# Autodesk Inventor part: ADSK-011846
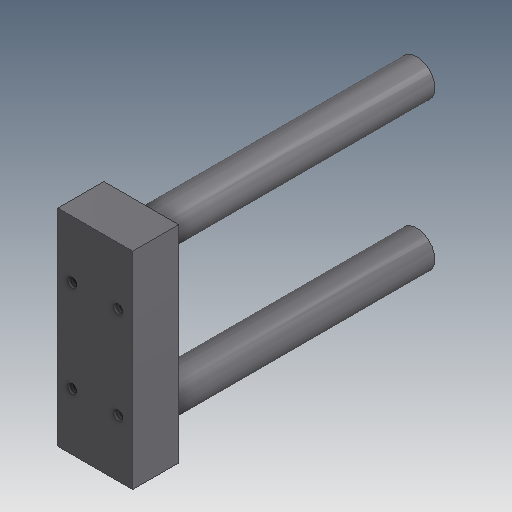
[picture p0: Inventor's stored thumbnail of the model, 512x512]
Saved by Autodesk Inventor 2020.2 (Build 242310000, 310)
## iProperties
Created: 1999-11
Part Number: ADSK-011846
Material: Acier doux
Document SubType Name: Modeling
Designer: sspink
Density: 7.86 g/cm^3
Appearance: Metal-Steel(Polish)
Mass: 210.486 g
Surface Area: 95.1232 cm^2
Volume: 26.7794 cm^3
Control State: 0
Master: False
Checked Out: False
Shininess: 0.0
Length Units: 11272
Angle Units: 11279
Time Units: 11290
Mass Units: 11286
Length Display Precision: 3
Angle Display Precision: 2
Compacted: True
Dimensions: 2,2x3,5x0,8 in
Mass: 0,464 lb
VLT_Material: Acier doux
Density: 0.0
Volumn: 0.0
Area: 0.0
PropertySet Name: Model Information
Author: sspink
Revision Number: -
Title: ADSK-011846
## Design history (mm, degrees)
node "Extrusion1" dims "d2" = 12.7, "d3" = 0
node "Extrusion2" dims "d7" = 76.073, "d8" = 0
node "Extrusion3" dims "d10" = 1.5748, "d11" = 0
node "Hole1" dims "d20" = 2.6416, "d21" = 9.525, "d22" = 6.35, "d23" = 60 deg, "d24" = 19.05, "d25" = 118 deg
node "Solide1"
node "Corps solides"
node "Corps surfaciques"
sketch "Sketch1"
  geometry: L1 (-21.899, 58.729)-(-1.262, 58.729) reference; L2 (-1.262, 58.729)-(-1.262, 1.732); L3 (-1.262, 1.732)-(-21.899, 1.732); L4 (-21.899, 1.732)-(-21.899, 58.729) reference
  constraints: 8 end point, 2 horizontal, 2 parallel, 1 perpendicular, 1 vertical
  dimensions: "d0" = 56.9976 distance of L3.end L1.start; "d1" = 20.6375 distance of L1.start L1.end
sketch "Sketch2"
  geometry: L1 (21.899, 58.729)-(21.899, 1.732) reference; L2 (1.262, 58.729)-(21.899, 58.729) reference; L3 (1.262, 1.732)-(1.262, 58.729) reference; L4 (21.899, 1.732)-(1.262, 1.732) reference; L5 (11.581, 58.729)-(11.581, 1.732); L6 (1.262, 30.231)-(21.899, 30.231); C1 r 5.004 at (11.581, 50.728); C2 r 5.004 at (11.581, 9.733)
  constraints: 4 end point, 4 midpoint, 2 centre point, 2 point on line, 1 equal radius
  dimensions: "d4" = 20.4978 distance from line of C1.centre L6; "d5" = 20.4978 distance from line of L6 C2.centre (= d4); "d6" = 10.0076 diameter of C1
sketch "Sketch3"
  geometry: C1 r 5.004 at (11.581, 50.728) reference; C2 r 5.004 at (11.581, 9.733) reference; C3 r 6.35 at (11.581, 50.728); C4 r 6.35 at (11.581, 9.733)
  constraints: 2 centre point, 2 coincident, 1 equal radius
  dimensions: "d9" = 12.7 diameter of C4
sketch "Sketch4"
  geometry: L1 (-21.899, 58.729)-(-1.262, 58.729) reference; L2 (-21.899, 1.732)-(-21.899, 58.729) reference; L3 (-1.262, 1.732)-(-21.899, 1.732) reference; L4 (-1.262, 58.729)-(-1.262, 1.732) reference; L5 (-11.581, 58.729)-(-11.581, 1.732); L6 (-21.899, 30.231)-(-1.262, 30.231); 4 further points
  constraints: 4 end point, 4 midpoint
  dimensions: "d12" = 12.7 distance from line of point (-5.231, 42.931) L6; "d13" = 12.7 distance from line of point (-17.931, 42.931) L6 (= d12); "d14" = 12.7 distance from line of point (-5.233, 17.531) L6 (= d12); "d15" = 12.7 distance from line of L6 point (-17.933, 17.531) (= d13); "d17" = 6.35 distance from line of L5 point (-17.931, 42.931) (= d16); "d18" = 6.35203 distance from line of point (-17.933, 17.531) L5; "d26" = 12.7 distance of point (-17.931, 42.931) point (-5.231, 42.931); "d27" = 12.7 distance of point (-17.933, 17.531) point (-5.233, 17.531)
other parameters: "d16" = 6.35
